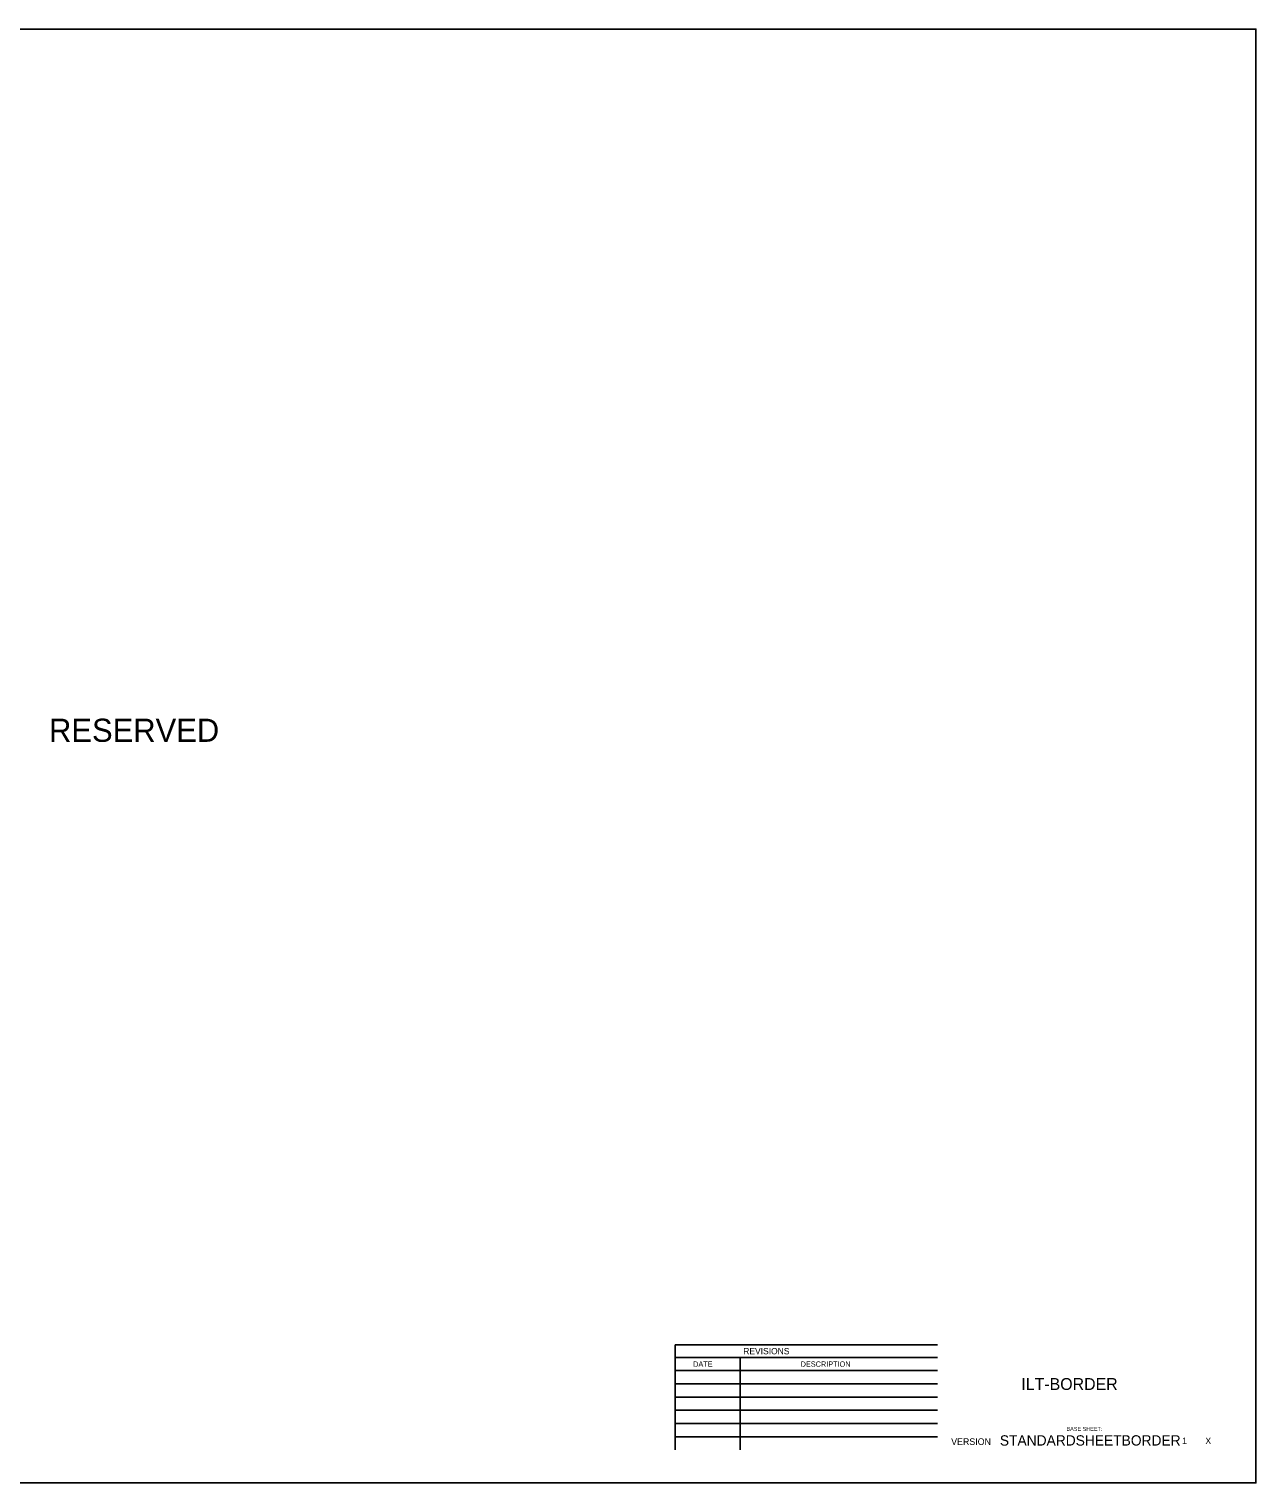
# Model space of a CAD drawing. Extents: x 0 to 2.83, y 0 to 1.83.
# Drawn here: x 1.286 to 2.833, y 0 to 1.833 of the extents above; entities that cross this region are included whole.
import ezdxf

# ---------------------------------------------------------------- set-up
doc = ezdxf.new("R2010")
doc.units = 0
for name, color, linetype in [('HS_Dimensions_and_Text', 7, 'Continuous'), ('SH_General_Details_Sheet_Number-ILTollway', 7, 'Continuous'), ('SH_General_Details_Sheet_Revision_Box-ILTollway', 7, 'Continuous'), ('SH_General_Details_Sheet_Standard-ILTollway', 7, 'Continuous'), ('SH_General_Details_Standard', 7, 'Continuous'), ('SH_General_Details_Title_Text-ILTollway', 7, 'Continuous'), ('SH_General_Details_Total_Sheet_Number-ILTollway', 7, 'Continuous'), ('SH_General_Details_Version_Text-ILTollway', 7, 'Continuous'), ('SH_Printer Plotting Border-ILTollway', 7, 'Continuous')]:
    doc.layers.add(name, color=color, linetype=linetype)

msp = doc.modelspace()

# ---------------------------------------------------------------- linework, layer by layer
at = {"layer": 'SH_General_Details_Sheet_Revision_Box-ILTollway'}
for p, q in [((2.1008, 0.0417), (2.1008, 0.1743)), ((2.4317, 0.1743), (2.1008, 0.1743)), ((2.4317, 0.158), (2.1008, 0.158)), ((2.1827, 0.158), (2.1827, 0.0417)), ((2.4317, 0.1417), (2.1008, 0.1417)), ((2.4317, 0.125), (2.1008, 0.125)), ((2.4317, 0.1083), (2.1008, 0.1083)), ((2.4317, 0.0917), (2.1008, 0.0917)), ((2.4317, 0.075), (2.1008, 0.075)), ((2.4317, 0.0583), (2.1008, 0.0583))]:
    msp.add_line(p, q, dxfattribs=at)
at = {"layer": 'SH_Printer Plotting Border-ILTollway'}
msp.add_lwpolyline([(0, 1.8333), (2.8333, 1.8333), (2.8333, 0), (0, 0)], close=True, dxfattribs=at)

# ---------------------------------------------------------------- texts
at = {"layer": 'HS_Dimensions_and_Text'}
msp.add_text('RESERVED', height=0.02917, dxfattribs=at).set_placement((1.3113, 0.9345))
at = {"layer": 'SH_General_Details_Sheet_Number-ILTollway'}
msp.add_text('1', height=0.00833, rotation=0, dxfattribs=at).set_placement((2.7402, 0.0489))
at = {"layer": 'SH_General_Details_Sheet_Revision_Box-ILTollway'}
for s, height, p in [('REVISIONS', 0.008, (2.1868, 0.1622)), ('DATE', 0.00667, (2.1236, 0.1465)), ('DESCRIPTION', 0.006667, (2.2592, 0.1465))]:
    msp.add_text(s, height=height, rotation=0, dxfattribs=at).set_placement(p)
at = {"layer": 'SH_General_Details_Sheet_Standard-ILTollway'}
msp.add_text('STANDARDSHEETBORDER', height=0.013, dxfattribs=at).set_placement((2.5104, 0.0471))
at = {"layer": 'SH_General_Details_Standard'}
msp.add_text('BASE SHEET:', height=0.005, rotation=0, dxfattribs=at).set_placement((2.5944, 0.0656))
at = {"layer": 'SH_General_Details_Title_Text-ILTollway'}
msp.add_text('ILT-BORDER', height=0.015, dxfattribs=at).set_placement((2.5375, 0.1172))
at = {"layer": 'SH_General_Details_Total_Sheet_Number-ILTollway'}
msp.add_text('X', height=0.00833, rotation=0, dxfattribs=at).set_placement((2.7695, 0.0489))
at = {"layer": 'SH_General_Details_Version_Text-ILTollway'}
msp.add_text('VERSION', height=0.00833, dxfattribs=at).set_placement((2.449, 0.0479))

doc.saveas('drawing.dxf')
